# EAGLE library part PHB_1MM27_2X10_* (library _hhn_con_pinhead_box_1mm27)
Pin Header Box-Type, 1.27mm/0.5"/50mil Pitch, 2x10 Circuits Note: see library description for an important note about THT-version
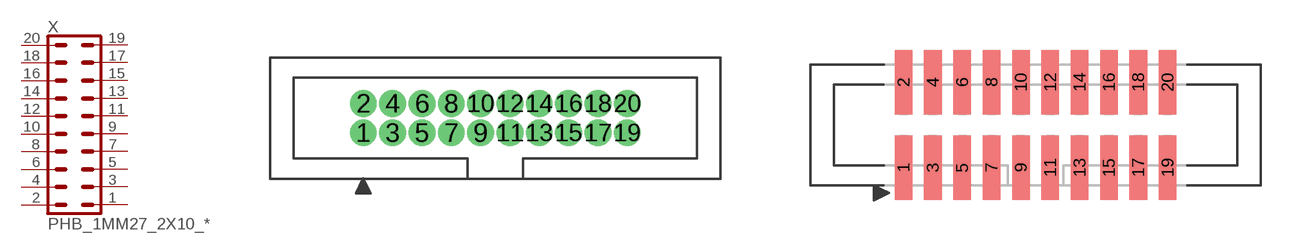
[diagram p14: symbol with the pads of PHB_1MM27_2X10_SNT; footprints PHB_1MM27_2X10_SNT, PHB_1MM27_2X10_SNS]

Designator prefix X

## PHB_1MM27_2X10_SNT  [PHB_1MM27_2X10_SNT]
1  1  pas
2  2  pas
3  3  pas
4  4  pas
5  5  pas
6  6  pas
7  7  pas
8  8  pas
9  9  pas
10  10  pas
11  11  pas
12  12  pas
13  13  pas
14  14  pas
15  15  pas
16  16  pas
17  17  pas
18  18  pas
19  19  pas
20  20  pas

## PHB_1MM27_2X10_SNS  [PHB_1MM27_2X10_SNS]
Pads as for PHB_1MM27_2X10_SNT

## Footprint PHB_1MM27_2X10_SNT (pad centres in mm)
Pin Header Box-Type, 1.27mm Pitch, 2x10 circuits, Straight, No Locking, THT Important Note: Diameter in this lbr is set to a specific value (NOT 'auto' = 0), this is ignored by actual eagle versions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
drill 0.65 pad 1 round: 1 -5.715,-0.635; 2 -5.715,0.635; 3 -4.445,-0.635; 4 -4.445,0.635; 5 -3.175,-0.635; 6 -3.175,0.635; 7 -1.905,-0.635; 8 -1.905,0.635; 9 -0.635,-0.635; 10 -0.635,0.635; 11 0.635,-0.635; 12 0.635,0.635; 13 1.905,-0.635; 14 1.905,0.635; 15 3.175,-0.635; 16 3.175,0.635; 17 4.445,-0.635; 18 4.445,0.635; 19 5.715,-0.635; 20 5.715,0.635

## Footprint PHB_1MM27_2X10_SNS (pad centres in mm)
Pin Header Box-Type, 1.27mm Pitch, 2x10 circuits, Straight, No Locking, SMT
smd 0.76 x 2.8: 1 -5.715,-1.85; 2 -5.715,1.85; 3 -4.445,-1.85; 4 -4.445,1.85; 5 -3.175,-1.85; 6 -3.175,1.85; 7 -1.905,-1.85; 8 -1.905,1.85; 9 -0.635,-1.85; 10 -0.635,1.85; 11 0.635,-1.85; 12 0.635,1.85; 13 1.905,-1.85; 14 1.905,1.85; 15 3.175,-1.85; 16 3.175,1.85; 17 4.445,-1.85; 18 4.445,1.85; 19 5.715,-1.85; 20 5.715,1.85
